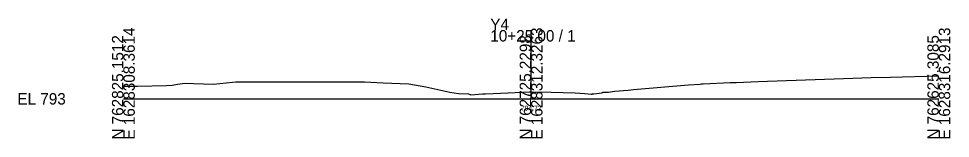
# Model space of a CAD drawing. Extents: x -26 to 203, y -10 to 3017.
# Drawn here: x -25.7 to 202.8, y 490.3 to 519.7 of the extents above; entities that cross this region are included whole.
import ezdxf

# ---------------------------------------------------------------- set-up
doc = ezdxf.new("R2010")
doc.units = 0
for name, color, linetype in [('Default', 7, 'Continuous'), ('Exist Cross Section Cell', 7, 'Continuous'), ('Exist XS Center Line Elevation Label', 7, 'Continuous'), ('Exist XS Ground Line', 7, 'Continuous')]:
    doc.layers.add(name, color=color, linetype=linetype)

msp = doc.modelspace()

# ---------------------------------------------------------------- linework, layer by layer
at = {"layer": 'Exist Cross Section Cell'}
for p, q in [((100, 500), (100, 516.85)), ((0, 500), (100, 500)), ((100, 500), (200, 500))]:
    msp.add_line(p, q, dxfattribs=at)
at = {"layer": 'Exist XS Ground Line'}
msp.add_lwpolyline([(0, 503.12), (3.49, 503.13), (10.6, 503.24), (11.98, 503.31), (13.31, 503.56), (15.15, 503.84), (17.16, 503.79), (22.08, 503.58), (26.74, 504.12), (27.57, 504.16), (29.75, 504.19), (39.75, 504.13), (45.7, 504.14), (56.04, 504.14), (59.15, 504.13), (63.68, 503.93), (70.05, 503.64), (74.16, 502.91), (80.09, 501.63), (82.21, 501.32), (84.62, 501.21), (85.19, 500.96), (88.1, 501.2), (88.78, 501.25), (94.36, 501.5), (99.65, 501.73), (100, 501.72), (104.9, 501.61), (110.79, 501.47), (113.08, 501.3), (114.78, 501.18), (115.06, 501.33), (115.1, 501.22), (115.4, 501.24), (117.38, 501.47), (117.57, 501.62), (118.87, 501.62), (119.02, 501.67), (120.44, 501.88), (123.84, 502.12), (125.12, 502.28), (138.6, 503.43), (141.45, 503.58), (141.82, 503.66), (142.19, 503.68), (148.79, 503.99), (149.37, 504), (149.79, 504.01), (150.28, 504.04), (155.71, 504.25), (176.61, 505.02), (183.42, 505.26), (188.16, 505.34), (200, 505.62)], dxfattribs=at)

# ---------------------------------------------------------------- texts
at = {"layer": 'Default'}
msp.add_text('-', height=0.0001, dxfattribs=at).set_placement((0, 500))
at = {"layer": 'Exist Cross Section Cell'}
for s, p in [('Y4', (90, 516.85)), ('10+25.00 / 1', (90, 514.05)), ('EL 793', (-26, 498.6))]:
    msp.add_text(s, height=2.8, dxfattribs=at).set_placement(p)
for s, p in [('E 1628308.3614', (2.8, 490)), ('E 1628312.3263', (102.8, 490)), ('E 1628316.2913', (202.8, 490)), ('N 762825.1512', (0, 490)), ('N 762725.2298', (100, 490)), ('N 762625.3085', (200, 490))]:
    msp.add_text(s, height=2.8, rotation=90, dxfattribs=at).set_placement(p)
at = {"layer": 'Exist XS Center Line Elevation Label'}
msp.add_text('794.72', height=1.2, dxfattribs=at).set_placement((97.51, 497.12))

doc.saveas('drawing.dxf')
